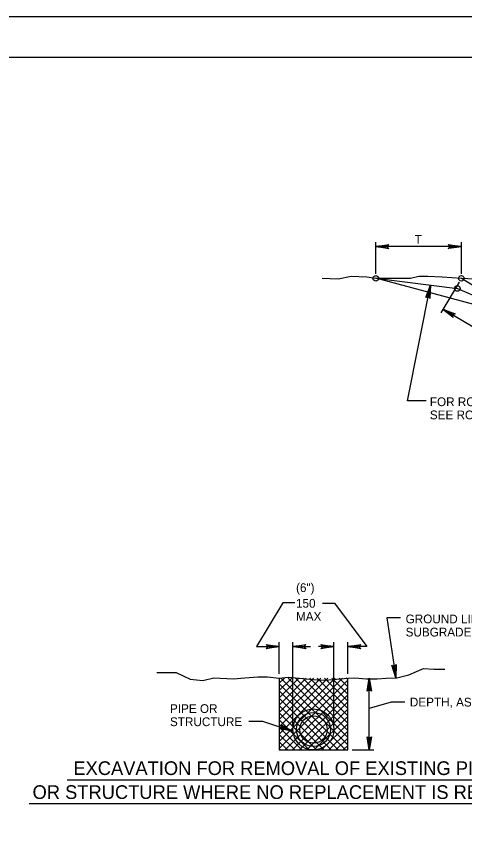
# Model space of a CAD drawing. Extents: x 240 to 1147, y 662 to 1256.
# Drawn here: x 597 to 760.7, y 956 to 1256 of the extents above; entities that cross this region are included whole.
import ezdxf

# ---------------------------------------------------------------- set-up
doc = ezdxf.new("R2010")
doc.units = 0
for name, color, linetype in [('1', 7, 'Continuous'), ('2', 7, 'Continuous'), ('3', 7, 'Continuous'), ('PLT-BNDY', 7, 'Continuous')]:
    doc.layers.add(name, color=color, linetype=linetype)

msp = doc.modelspace()

# ---------------------------------------------------------------- linework, layer by layer
at = {"layer": '1'}
for points in [[(1065.4425, 677.018625), (1065.4425, 1241.018625), (279.4425, 1241.018625), (279.4425, 677.018625), (1065.4425, 677.018625), (1065.4425, 703.377625), (865.4425, 703.377625), (865.4425, 768.055125), (1065.4425, 768.055125), (1065.4425, 797.018625), (865.4425, 797.018625), (865.4425, 677.018625), (944.244, 677.018625), (944.244, 703.377625), (944.244, 677.018625), (1021.244, 677.018625), (1021.244, 703.377625), (1021.244, 691.061125), (1065.4425, 691.061125)], [(732.81425, 1171.359375), (732.6455, 1171.688625), (728.27275, 1171.930125), (732.81425, 1171.359375), (733.04775, 1171.161375), (728.27275, 1171.930125), (732.6415, 1172.146875), (732.79975, 1172.471875), (728.27275, 1171.930125), (733.04775, 1172.688625), (732.79975, 1172.471875)], [(754.983, 1172.498875), (755.15175, 1172.171875), (759.52275, 1171.930125), (754.983, 1172.498875), (754.74975, 1172.698875), (759.52275, 1171.930125), (755.156, 1171.713625), (754.9955, 1171.388625), (759.52275, 1171.930125), (754.74975, 1171.171875), (754.9955, 1171.388625)], [(746.804, 1153.486375), (747.16025, 1153.586375), (748.24775, 1157.828125), (746.804, 1153.486375), (746.56225, 1153.296875), (748.24775, 1157.828125), (747.608, 1153.501125), (747.8955, 1153.282375), (748.24775, 1157.828125), (748.06225, 1152.998875), (747.8955, 1153.282375)], [(756.3955, 1146.292625), (756.4205, 1146.661375), (752.7955, 1149.117625), (756.3955, 1146.292625), (756.4935, 1146.003125), (752.7955, 1149.117625), (756.65175, 1147.055125), (756.956, 1147.253125), (752.7955, 1149.117625), (757.279, 1147.313625), (756.956, 1147.253125)], [(688.4705, 1026.330125), (688.64125, 1026.000875), (693.01225, 1025.759125), (688.4705, 1026.330125), (688.23925, 1026.530125), (693.01225, 1025.759125), (688.6435, 1025.544625), (688.485, 1025.219625), (693.01225, 1025.759125), (688.23925, 1025.000875), (688.485, 1025.219625)], [(702.55375, 1025.190375), (702.383, 1025.519625), (698.01225, 1025.759125), (702.55375, 1025.190375), (702.785, 1024.990375), (698.01225, 1025.759125), (702.381, 1025.975875), (702.53925, 1026.300875), (698.01225, 1025.759125), (702.785, 1026.517625), (702.53925, 1026.300875)], [(708.4705, 1026.330125), (708.64125, 1026.000875), (713.01225, 1025.759125), (708.4705, 1026.330125), (708.23925, 1026.530125), (713.01225, 1025.759125), (708.6435, 1025.544625), (708.485, 1025.219625), (713.01225, 1025.759125), (708.23925, 1025.000875), (708.485, 1025.219625)], [(722.55375, 1025.190375), (722.383, 1025.519625), (718.01225, 1025.759125), (722.55375, 1025.190375), (722.785, 1024.990375), (718.01225, 1025.759125), (722.381, 1025.975875), (722.53925, 1026.300875), (718.01225, 1025.759125), (722.785, 1026.517625), (722.53925, 1026.300875)], [(735.51225, 1018.942625), (735.21225, 1018.725875), (735.62675, 1014.367625), (735.51225, 1018.942625), (735.67475, 1019.200875), (735.62675, 1014.367625), (734.76225, 1018.652875), (734.41625, 1018.763375), (735.62675, 1014.367625), (734.16425, 1018.973875), (734.41625, 1018.763375)], [(725.333, 1009.713375), (725.66225, 1009.884125), (725.90375, 1014.255125), (725.333, 1009.713375), (725.135, 1009.482125), (725.90375, 1014.255125), (726.1205, 1009.886375), (726.4455, 1009.727875), (725.90375, 1014.255125), (726.66225, 1009.482125), (726.4455, 1009.727875)], [(693.898, 996.876375), (693.9555, 996.512125), (698.035, 994.919625), (693.898, 996.876375), (693.7385, 997.138625), (698.035, 994.919625), (693.817, 996.075125), (693.56425, 995.815875), (698.035, 994.919625), (693.262, 995.686625), (693.56425, 995.815875)], [(726.47475, 992.546625), (726.1455, 992.375875), (725.90375, 988.005125), (726.47475, 992.546625), (726.6725, 992.777875), (725.90375, 988.005125), (725.68725, 992.373875), (725.36225, 992.532125), (725.90375, 988.005125), (725.1455, 992.777875), (725.36225, 992.532125)]]:
    msp.add_lwpolyline(points, dxfattribs=at)
at = {"layer": '2'}
for p, q in [((728.27275, 1161.930125), (728.27275, 1173.530125)), ((759.52275, 1161.930125), (759.52275, 1173.530125)), ((759.52275, 1171.930125), (728.27275, 1171.930125)), ((784.52275, 1145.330125), (728.27275, 1160.330125)), ((728.27275, 1160.330125), (758.08525, 1156.594875)), ((758.69975, 1158.959375), (751.97275, 1147.746875)), ((759.52275, 1160.330125), (784.52275, 1145.330125)), ((739.8405, 1115.550625), (748.24775, 1157.828125)), ((758.08525, 1156.594875), (784.52275, 1145.330125)), ((777.7955, 1134.117625), (752.7955, 1149.117625)), ((746.665, 1115.550625), (739.8405, 1115.550625)), ((693.01225, 1015.855125), (693.01225, 1027.359125)), ((698.01225, 997.105125), (698.01225, 1027.359125)), ((713.01225, 997.105125), (713.01225, 1027.359125)), ((718.01225, 1015.855125), (718.01225, 1027.359125)), ((684.66225, 1025.759125), (693.01225, 1025.759125)), ((698.01225, 1025.759125), (704.431, 1025.759125)), ((713.01225, 1025.759125), (707.32875, 1025.759125)), ((725.05175, 1025.759125), (718.01225, 1025.759125)), ((693.01225, 991.150875), (716.11625, 1014.255125)), ((693.01225, 993.802875), (713.46425, 1014.255125)), ((693.01225, 996.455125), (710.81425, 1014.255125)), ((693.01225, 999.105125), (708.16225, 1014.255125)), ((693.01225, 1001.757125), (705.51, 1014.255125)), ((693.01225, 1004.409125), (702.858, 1014.255125)), ((693.01225, 1007.061375), (700.206, 1014.255125)), ((693.01225, 1009.711375), (697.556, 1014.255125)), ((693.01225, 1012.363375), (694.90375, 1014.255125)), ((718.01225, 989.875875), (693.633, 1014.255125)), ((718.01225, 992.525875), (696.283, 1014.255125)), ((718.01225, 995.177875), (698.935, 1014.255125)), ((718.01225, 997.830125), (701.58725, 1014.255125)), ((718.01225, 1000.482125), (704.23925, 1014.255125)), ((718.01225, 1003.132125), (706.88925, 1014.255125)), ((718.01225, 1005.784125), (709.54125, 1014.255125)), ((718.01225, 1008.436375), (712.1935, 1014.255125)), ((718.01225, 1011.088375), (714.8455, 1014.255125)), ((718.01225, 1013.740375), (717.4975, 1014.255125)), ((725.90375, 988.005125), (725.90375, 1014.255125)), ((693.01225, 988.498875), (718.01225, 1013.498875)), ((717.231, 988.005125), (693.01225, 1012.223875)), ((714.57875, 988.005125), (693.01225, 1009.571625)), ((695.1705, 988.005125), (718.01225, 1010.846625)), ((697.8225, 988.005125), (718.01225, 1008.194625)), ((711.92675, 988.005125), (693.01225, 1006.919625)), ((700.4725, 988.005125), (718.01225, 1005.544625)), ((709.27475, 988.005125), (693.01225, 1004.267625)), ((703.12475, 988.005125), (718.01225, 1002.892625)), ((706.62475, 988.005125), (693.01225, 1001.617625)), ((705.77675, 988.005125), (718.01225, 1000.240375)), ((681.92125, 998.500125), (686.92125, 998.500125)), ((686.92125, 998.500125), (698.035, 994.919625)), ((703.9725, 988.005125), (693.01225, 998.965375)), ((701.3205, 988.005125), (693.01225, 996.313375)), ((708.42875, 988.005125), (718.01225, 997.588375)), ((698.6685, 988.005125), (693.01225, 993.661375)), ((711.07875, 988.005125), (718.01225, 994.938375)), ((696.01625, 988.005125), (693.01225, 991.009125)), ((713.731, 988.005125), (718.01225, 992.286375)), ((693.36625, 988.005125), (693.01225, 988.359125)), ((716.383, 988.005125), (718.01225, 989.634125)), ((719.61225, 988.005125), (727.50375, 988.005125)), ((615.55375, 977.152875), (811.5685, 977.152875)), ((601.731, 968.477875), (825.97875, 968.477875))]:
    msp.add_line(p, q, dxfattribs=at)
for points in [[(708.633, 1160.409375), (714.56425, 1160.167625), (719.31025, 1161.128125), (725.004, 1160.888625), (728.27275, 1160.330125), (740.90175, 1160.409375), (743.98725, 1161.128125), (747.31025, 1161.128125), (752.529, 1160.888625), (759.52275, 1160.330125), (764.156, 1160.167625)], [(698.6645, 1041.792625), (694.3185, 1041.792625), (684.66225, 1025.759125)], [(708.8555, 1041.619625), (713.181, 1041.619625), (725.05175, 1025.759125)], [(737.3225, 1036.275875), (732.3225, 1036.275875), (735.62675, 1014.367625)], [(648.36225, 1016.277875), (655.34975, 1016.277875), (660.46225, 1013.863375), (665.06225, 1013.346625), (669.15375, 1014.382125), (676.14125, 1014.036375), (680.40175, 1014.382125), (685.1725, 1014.725875), (688.75175, 1014.725875), (693.01225, 1014.255125), (696.24975, 1014.555125), (708.181, 1013.519625), (711.07675, 1013.692625), (718.01225, 1014.255125), (720.6205, 1014.382125), (724.881, 1014.036375), (728.80175, 1014.036375), (732.03925, 1014.209125), (735.958, 1014.382125), (740.38925, 1015.415375), (743.11625, 1016.623875), (745.6725, 1017.830125), (749.4225, 1017.484125), (753.51225, 1017.484125)], [(693.01225, 1014.255125), (693.01225, 1014.255125), (693.01225, 988.005125), (718.01225, 988.005125), (718.01225, 1014.255125)], [(738.856, 1005.417625), (733.856, 1005.417625), (725.90375, 1003.175875)]]:
    msp.add_lwpolyline(points, dxfattribs=at)
for centre, radius in [((728.273167, 1160.331208), 1.015435), ((759.523167, 1160.331208), 1.015435), ((758.084667, 1156.594958), 1.015435), ((705.51225, 995.505125), 7.5), ((705.51225, 995.505125), 6.25), ((705.51225, 995.505125), 5)]:
    msp.add_circle(centre, radius, dxfattribs=at)
at = {"layer": 'PLT-BNDY'}
msp.add_lwpolyline([(240.4425, 1256.018625), (1081.4425, 1256.018625), (1081.4425, 662.018625), (240.4425, 662.018625)], close=True, dxfattribs=at)

# ---------------------------------------------------------------- texts
at = {"layer": '1'}
for s, height, p in [('(6")', 3.1999995, (699.1545, 1045.716625)), ('EXCAVATION FOR REMOVAL OF EXISTING PIPE', 4.9999995, (617.81625, 978.861375)), ('OR STRUCTURE WHERE NO REPLACEMENT IS REQUIRED', 4.9999995, (602.91625, 970.111375))]:
    msp.add_text(s, height=height, dxfattribs=at).set_placement(p)
at = {"layer": '2'}
for s, height, p in [('T', 3.199988, (742.47475, 1172.955125)), ('DEPTH, AS REQUIRED', 3.1999875, (740.7225, 1003.894625))]:
    msp.add_text(s, height=height, dxfattribs=at).set_placement(p)
at = {"layer": '3'}
for s, p in [('FOR ROUNDING DETAILS,', (748.02925, 1113.629125)), ('SEE ROUNDING OF CUT SLOPES.', (748.02925, 1108.829125)), ('150', (699.13575, 1039.994375)), ('MAX', (699.13575, 1035.194375)), ('GROUND LINE OR', (739.1725, 1034.275875)), ('SUBGRADE ELEVATION', (739.1725, 1029.475875)), ('PIPE OR', (653.11, 1001.521625)), ('STRUCTURE', (653.11, 996.721625))]:
    msp.add_text(s, height=3.1999875, dxfattribs=at).set_placement(p)

doc.saveas('drawing.dxf')
